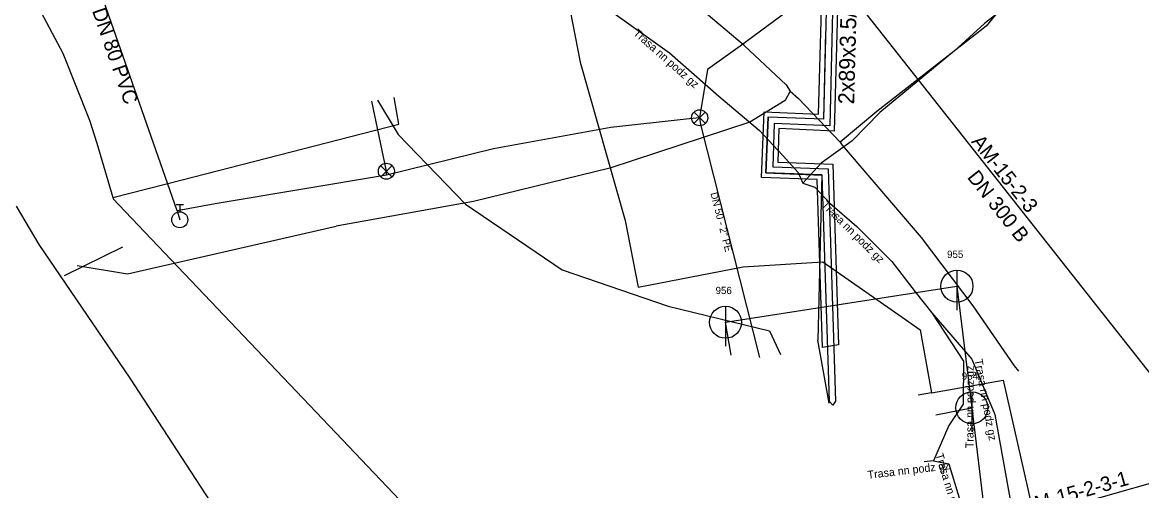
# Model space of a CAD drawing. Extents: x -492431 to -49223, y -1127123 to -112687.
# Drawn here: x -492368.2 to -492298.3, y -1127017.5 to -1126988.2 of the extents above; entities that cross this region are included whole.
import ezdxf

# ---------------------------------------------------------------- set-up
doc = ezdxf.new("R2010")
doc.units = 0
for name, color, linetype in [('Vrstva 1', 7, 'Continuous'), ('Vrstva 11', 7, 'Continuous'), ('Vrstva 15', 7, 'Continuous'), ('Vrstva 17', 7, 'Continuous'), ('Vrstva 19', 7, 'Continuous'), ('Vrstva 20', 7, 'Continuous'), ('Vrstva 22', 7, 'Continuous'), ('Vrstva 24', 7, 'Continuous'), ('Vrstva 25', 7, 'Continuous'), ('Vrstva 26', 7, 'Continuous'), ('Vrstva 35', 7, 'Continuous'), ('Vrstva 44', 7, 'Continuous'), ('Vrstva 45', 7, 'Continuous'), ('Vrstva 49', 7, 'Continuous'), ('Vrstva 5', 7, 'Continuous'), ('Vrstva 9', 7, 'Continuous')]:
    doc.layers.add(name, color=color, linetype=linetype)

msp = doc.modelspace()

# ---------------------------------------------------------------- linework, layer by layer
at = {"layer": 'Vrstva 1'}
for points in [[(-492325.249, -1126898.739), (-492328.46, -1126899.749), (-492340.823, -1126903.639), (-492342.635, -1126904.209), (-492340.846, -1126909.212), (-492340.001, -1126912.396), (-492365.716, -1126927.205), (-492383.843, -1126938.777), (-492388.933, -1126942.125), (-492392.447, -1126948.035), (-492388.723, -1126953.769), (-492383.343, -1126961.208), (-492380.745, -1126965.156), (-492371.24, -1126979.603), (-492365.631, -1126990.113), (-492363.978, -1126994.289), (-492363.52, -1126995.731), (-492362.52, -1126999.134), (-492362.499, -1126999.206), (-492361.744, -1127000), (-492348.578, -1127013.843), (-492336.22, -1127026.859)], [(-492362.52, -1126999.134), (-492358.184, -1126998.021), (-492344.649, -1126994.545), (-492344.941, -1126992.87)]]:
    msp.add_lwpolyline(points, dxfattribs=at)
at = {"layer": 'Vrstva 11'}
for points in [[(-492337.27, -1126978.85), (-492334.41, -1126985.09), (-492333.33, -1126990.66), (-492330.52, -1127000.57), (-492329.71, -1127004.74), (-492323.14, -1127003.47)], [(-492323.14, -1127003.47), (-492318.16, -1127003.15), (-492313, -1127006.75), (-492312.08, -1127007.4), (-492311.39, -1127011.34)], [(-492311.39, -1127011.34), (-492306.9, -1127010.55), (-492303.71, -1127024.71), (-492309.4, -1127027.64), (-492319.56, -1127033.38)], [(-492311.39, -1127011.34), (-492312.21, -1127011.49)]]:
    msp.add_lwpolyline(points, dxfattribs=at)
at = {"layer": 'Vrstva 15'}
for p, q in [((-492319.259, -1126982.82), (-492293.327, -1127015.749)), ((-492324.251, -1127006.93), (-492309.793, -1127004.673)), ((-492309.793, -1127004.673), (-492308.864, -1127012.278)), ((-492323.887, -1127008.991), (-492324.251, -1127006.93)), ((-492311.103, -1127012.704), (-492308.864, -1127012.278)), ((-492308.864, -1127012.278), (-492307.936, -1127019.882)), ((-492307.936, -1127019.882), (-492293.327, -1127015.749))]:
    msp.add_line(p, q, dxfattribs=at)
at = {"layer": 'Vrstva 17'}
for p, q in [((-492309.793, -1127003.673), (-492309.793, -1127006.173)), ((-492324.251, -1127005.93), (-492324.251, -1127008.43)), ((-492308.864, -1127011.278), (-492308.864, -1127013.778))]:
    msp.add_line(p, q, dxfattribs=at)
for centre in [(-492309.793, -1127004.673), (-492324.251, -1127006.93), (-492308.864, -1127012.278)]:
    msp.add_circle(centre, 1, dxfattribs=at)
at = {"layer": 'Vrstva 20'}
msp.add_line((-492358.496, -1126999.968), (-492358.33, -1127000.52), dxfattribs=at)
for points in [[(-492358.496, -1126999.968), (-492364.96, -1126981.41), (-492366.67, -1126975.11), (-492367.57, -1126971.21), (-492369.75, -1126961.18), (-492369.82, -1126960.77)], [(-492251.966, -1126984.002), (-492252.867, -1126984.562), (-492256.417, -1126985.913), (-492263.134, -1126989.093), (-492271.494, -1126992.401), (-492271.919, -1126991.405), (-492277.913, -1126970.81), (-492278.388, -1126969.283), (-492287.981, -1126972.121), (-492294.895, -1126974.083), (-492300.39, -1126975.871), (-492310.81, -1126979.945), (-492316.118, -1126984.31), (-492323.327, -1126989.676), (-492325.365, -1126991.119)], [(-492325.365, -1126991.119), (-492325.862, -1126994.141), (-492326.705, -1126994.241), (-492331.409, -1126994.742), (-492338.736, -1126996.091), (-492345.411, -1126997.731), (-492356.118, -1126999.525), (-492358.496, -1126999.968)], [(-492345.411, -1126997.731), (-492345.43, -1126997.489), (-492346.329, -1126993.112)], [(-492325.862, -1126994.141), (-492325.811, -1126994.564), (-492322.132, -1127009.12)]]:
    msp.add_lwpolyline(points, dxfattribs=at)
at = {"layer": 'Vrstva 22'}
for p, q in [((-492326.212, -1126994.491), (-492325.512, -1126993.791)), ((-492325.512, -1126994.491), (-492326.212, -1126993.791)), ((-492345.78, -1126997.839), (-492345.08, -1126997.139)), ((-492345.08, -1126997.839), (-492345.78, -1126997.139)), ((-492358.555, -1126999.57), (-492358.105, -1126999.57)), ((-492358.33, -1126999.57), (-492358.33, -1127000.02))]:
    msp.add_line(p, q, dxfattribs=at)
for centre, radius in [((-492325.862, -1126994.141), 0.5), ((-492325.862, -1126994.141), 0.025), ((-492345.43, -1126997.489), 0.5), ((-492345.43, -1126997.489), 0.025), ((-492358.33, -1127000.52), 0.5)]:
    msp.add_circle(centre, radius, dxfattribs=at)
at = {"layer": 'Vrstva 25'}
for p, q in [((-492368.56, -1126999.68), (-492367.13, -1127002.07)), ((-492367.13, -1127002.07), (-492361.46, -1127010.42)), ((-492365.54, -1127004), (-492361.88, -1127002.22)), ((-492361.46, -1127010.42), (-492355.47, -1127019.6))]:
    msp.add_line(p, q, dxfattribs=at)
at = {"layer": 'Vrstva 26'}
for p, q in [((-492323.08, -1126989.62), (-492328.61, -1126984.96)), ((-492307.04, -1126987.28), (-492307.97, -1126988.41)), ((-492307.97, -1126988.41), (-492314.8, -1126993.76)), ((-492320.46, -1126992.09), (-492323.08, -1126989.62)), ((-492320.46, -1126992.09), (-492320.2, -1126992.48)), ((-492320.2, -1126992.48), (-492320.52, -1126993.07)), ((-492320.2, -1126992.48), (-492319.69, -1126992.94)), ((-492320.52, -1126993.07), (-492322.72, -1126994.41)), ((-492317.08, -1126995.66), (-492319.69, -1126992.94)), ((-492314.8, -1126993.76), (-492317.08, -1126995.66)), ((-492322.72, -1126994.41), (-492331.47, -1126997.3)), ((-492317.08, -1126995.66), (-492316.97, -1126995.85)), ((-492316.97, -1126995.85), (-492312.02, -1127001.63)), ((-492331.47, -1126997.3), (-492339.98, -1126999.37)), ((-492339.98, -1126999.37), (-492348.56, -1127000.91)), ((-492361.59, -1127003.89), (-492348.56, -1127000.91)), ((-492312.02, -1127001.63), (-492308.8, -1127005.9)), ((-492364.74, -1127003.38), (-492361.59, -1127003.89)), ((-492308.8, -1127005.9), (-492306.22, -1127009.65)), ((-492306.22, -1127009.65), (-492305.95, -1127009.99))]:
    msp.add_line(p, q, dxfattribs=at)
at = {"layer": 'Vrstva 35'}
msp.add_lwpolyline([(-492345.99, -1126993.05), (-492344.69, -1126995.2), (-492340.48, -1126999.54), (-492334.45, -1127003.65), (-492327.82, -1127005.93), (-492321.5, -1127007.47), (-492320.82, -1127008.95)], dxfattribs=at)
at = {"layer": 'Vrstva 44'}
for p, q in [((-492318.43, -1126993.91), (-492318.12, -1126982.03)), ((-492317.12, -1126981.96), (-492317.46, -1126994.98)), ((-492322.01, -1126997.88), (-492321.83, -1126993.77)), ((-492321.83, -1126993.77), (-492318.43, -1126993.91)), ((-492320.91, -1126994.82), (-492320.99, -1126996.92)), ((-492317.46, -1126994.98), (-492320.91, -1126994.82)), ((-492320.99, -1126996.92), (-492317.54, -1126997.04)), ((-492317.54, -1126997.04), (-492317.19, -1127008.34)), ((-492318.52, -1126998.01), (-492322.01, -1126997.88)), ((-492318.18, -1127008.51), (-492318.52, -1126998.01)), ((-492317.19, -1127008.34), (-492318.18, -1127008.51))]:
    msp.add_line(p, q, dxfattribs=at)
at = {"layer": 'Vrstva 45'}
for p, q in [((-492317.82, -1126982), (-492318.13, -1126994.23)), ((-492317.42, -1126981.96), (-492317.74, -1126994.64)), ((-492318, -1126988.8), (-492318.13, -1126994.22)), ((-492321.72, -1126997.59), (-492321.59, -1126994.09)), ((-492321.59, -1126994.1), (-492321.72, -1126997.59)), ((-492321.59, -1126994.09), (-492318.13, -1126994.22)), ((-492318.13, -1126994.23), (-492321.59, -1126994.1)), ((-492318.09, -1126993.7), (-492318.09, -1126993.7)), ((-492321.2, -1126994.51), (-492321.3, -1126997.21)), ((-492317.74, -1126994.64), (-492321.2, -1126994.51)), ((-492318.23, -1126997.72), (-492321.72, -1126997.59)), ((-492321.72, -1126997.59), (-492318.23, -1126997.73)), ((-492321.3, -1126997.21), (-492317.84, -1126997.34)), ((-492317.84, -1126997.34), (-492317.37, -1127011.85)), ((-492318.23, -1126997.72), (-492318.49, -1127008.05)), ((-492318.23, -1126997.73), (-492317.77, -1127011.86)), ((-492318.34, -1127002.19), (-492318.34, -1127002.19)), ((-492317.77, -1127011.98), (-492318.49, -1127008.05)), ((-492317.77, -1127011.86), (-492317.55, -1127012.1)), ((-492317.37, -1127011.85), (-492317.55, -1127012.1))]:
    msp.add_line(p, q, dxfattribs=at)
at = {"layer": 'Vrstva 5'}
for points in [[(-492295.19, -1126971.61), (-492297.69, -1126972.2), (-492301.37, -1126973.31), (-492308.91, -1126976.48), (-492312.71, -1126978.52), (-492313.47, -1126979.44), (-492313.21, -1126980.52), (-492309.8, -1126983.48), (-492308.71, -1126984.73), (-492306.89, -1126986.47), (-492306.85, -1126987.29), (-492308.07, -1126988.26), (-492309.94, -1126989.95), (-492314.61, -1126993.81), (-492316.34, -1126995.59), (-492318.28, -1126996.99), (-492319.42, -1126998.23)], [(-492335.56, -1126985.96), (-492331.46, -1126987.43), (-492327.75, -1126990.08), (-492324.66, -1126992.8), (-492322.12, -1126994.94), (-492320.69, -1126996.48), (-492319.72, -1126997.57), (-492319.42, -1126998.23)], [(-492319.42, -1126998.23), (-492318.66, -1126998.48), (-492317.74, -1126999.48), (-492316.05, -1127000.95), (-492313.85, -1127003.12), (-492312.41, -1127005.03), (-492311.36, -1127006.34)], [(-492311.36, -1127006.34), (-492309.39, -1127009.35), (-492309.4, -1127012.04), (-492310.31, -1127013.38), (-492311.26, -1127015.58)], [(-492311.36, -1127006.34), (-492308.86, -1127009.23), (-492307.42, -1127012.69), (-492306.42, -1127018.26), (-492306.18, -1127020.77)], [(-492311.26, -1127015.58), (-492311.85, -1127015.65)], [(-492311.26, -1127015.58), (-492310.29, -1127015.78), (-492309.38, -1127018.8), (-492308.01, -1127019.07), (-492306.8, -1127019.64), (-492306.18, -1127020.77)]]:
    msp.add_lwpolyline(points, dxfattribs=at)

# ---------------------------------------------------------------- texts
at = {"layer": 'Vrstva 19'}
for s, height, rotation, p in [('AM-15-2-3', 0.9099, 308.22088, (-492308.934, -1126995.649)), ('DN 300 B', 0.9099, 308.22088, (-492309.193, -1126997.873)), ('AM-15-2-3-1', 0.90989, 15.79662, (-492305.572, -1127018.931))]:
    msp.add_text(s, height=height, rotation=rotation, dxfattribs=at).set_placement(p)
for s, p in [('955', (-492310.41, -1127002.909)), ('956', (-492324.868, -1127005.166)), ('954', (-492309.492, -1127010.514))]:
    msp.add_text(s, height=0.4549, dxfattribs=at).set_placement(p)
at = {"layer": 'Vrstva 24'}
for s, height, rotation, p in [('DN 80 PVC', 0.9099, 289.20403, (-492363.821, -1126987.447)), ("DN 50 - 2'' PE", 0.455, 284.18395, (-492325.193, -1126998.864))]:
    msp.add_text(s, height=height, rotation=rotation, dxfattribs=at).set_placement(p)
at = {"layer": 'Vrstva 49'}
msp.add_text('2x89x3.5/ 2"/ 5x4"', height=1, rotation=88.52396, dxfattribs=at).set_placement((-492316.216, -1126993.311))
at = {"layer": 'Vrstva 9'}
for rotation, p in [(318.64386, (-492330.048, -1126988.923)), (315.39333, (-492318.296, -1126999.649)), (280.17807, (-492308.694, -1127009.274)), (89.78701, (-492308.76, -1127014.801)), (286.76884, (-492311.144, -1127015.201)), (6.76618, (-492315.345, -1127016.719))]:
    msp.add_text('Trasa nn podz gz', height=0.5, rotation=rotation, dxfattribs=at).set_placement(p)

doc.saveas('drawing.dxf')
